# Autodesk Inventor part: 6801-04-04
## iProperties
Author: Administrator
Shininess: 64.0
Angle Display Precision: 2
Document Length Units: 11272
Document Angle Units: 11286
Document Time Units: 11279
Document Mass Units: 11290
Document Length Units Precision: 3
Document Angle Units Precision: 2
Compacted: True
PropertySet Name: _Private Model Information
Created: 2001-12
Part Number: 6801-04-04
Description: Jic(-4) to Male O-ring (-4), 90 degrees
Document SubType Name: Modeling
Designer: Administrator
Control State: 0
Master: False
Checked Out: False
PropertySet Name: Design Tracking Control
Density: 0.0
Volumn: 0.0
Area: 0.0
PropertySet Name: Model Information
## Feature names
1. Extrusion1
2. Extrusion2
3. Revolution1
4. Revolution2
5. Fillet1
6. Revolution3
7. Extrusion3
8. Revolution4
9. Extrusion4
10. Extrusion5
11. Chamfer1
12. Sweep1
13. Revolution7
